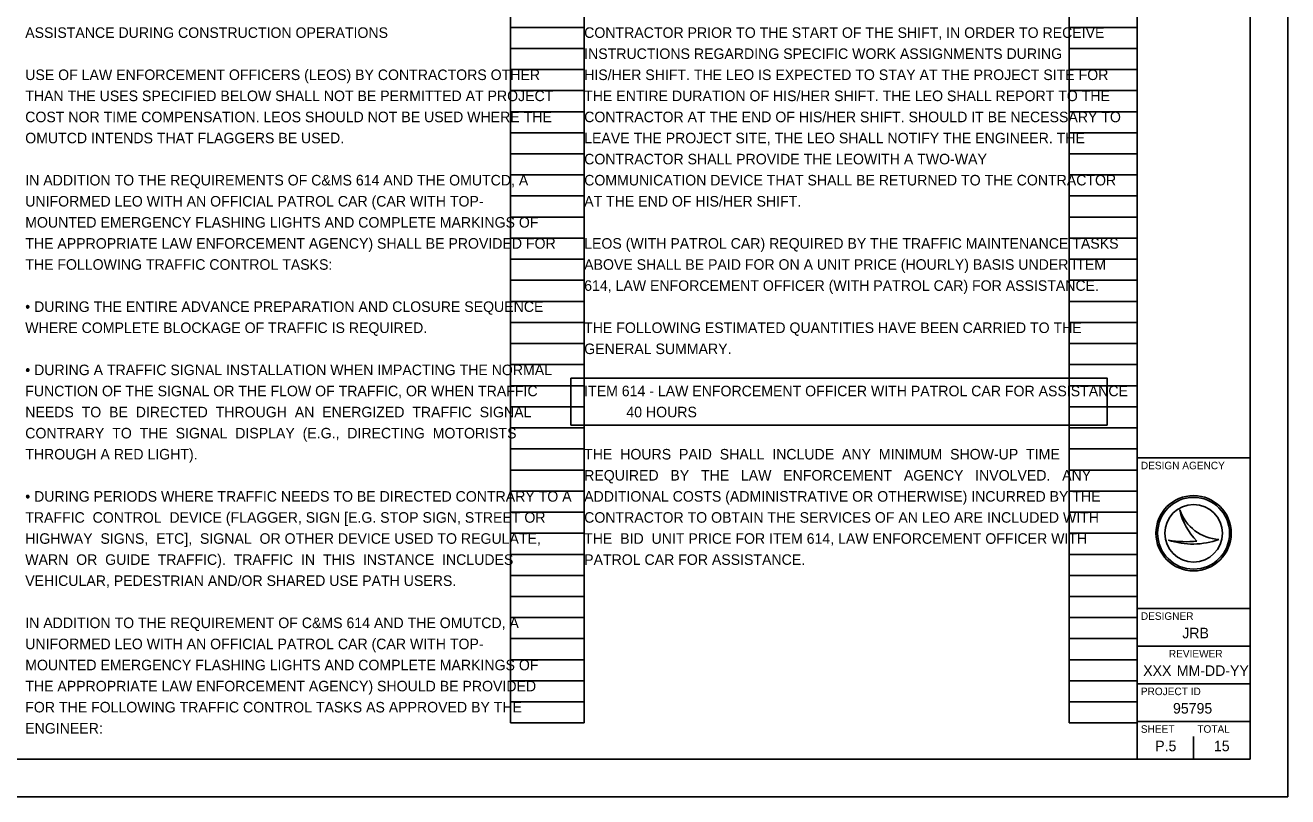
# Model space of a CAD drawing. Extents: x 0 to 34, y 0 to 22.
# Drawn here: x 17.24 to 34, y 0 to 10.25 of the extents above; entities that cross this region are included whole.
import ezdxf

# ---------------------------------------------------------------- set-up
doc = ezdxf.new("R2010")
doc.units = 0
for name, color, linetype in [('SC_Scratch1', 7, 'Continuous'), ('SH_Border', 7, 'Continuous'), ('SH_Cut_Line', 7, 'Continuous'), ('SH_Data', 7, 'Continuous'), ('SH_Text', 7, 'Continuous')]:
    doc.layers.add(name, color=color, linetype=linetype)

msp = doc.modelspace()

# ---------------------------------------------------------------- linework, layer by layer
at = {"layer": 'SC_Scratch1'}
msp.add_lwpolyline([(24.484, 5.562), (31.602, 5.562), (31.602, 4.936), (24.484, 4.936)], close=True, dxfattribs=at)
at = {"layer": 'SH_Border'}
for p, q in [((32, 0.5), (32, 21.5)), ((32, 4.5), (33.5, 4.5)), ((32, 2.5), (33.5, 2.5)), ((32, 2), (33.5, 2)), ((32, 1.5), (33.5, 1.5)), ((32, 1), (33.5, 1))]:
    msp.add_line(p, q, dxfattribs=at)
msp.add_lwpolyline([(1.5, 21.5), (33.5, 21.5), (33.5, 0.5), (1.5, 0.5)], close=True, dxfattribs=at)
at = {"layer": 'SH_Cut_Line'}
msp.add_lwpolyline([(0, 0), (34, 0), (34, 22), (0, 22)], close=True, dxfattribs=at)
at = {"layer": 'SH_Data'}
for p, q in [((23.68, 0.98), (23.68, 21.14)), ((24.66, 0.98), (24.66, 21.14)), ((31.1, 0.98), (31.1, 21.14)), ((32, 0.98), (32, 21.14)), ((23.68, 10.22), (24.66, 10.22)), ((31.1, 10.22), (32, 10.22)), ((23.68, 9.94), (24.66, 9.94)), ((31.1, 9.94), (32, 9.94)), ((23.68, 9.66), (24.66, 9.66)), ((31.1, 9.66), (32, 9.66)), ((23.68, 9.38), (24.66, 9.38)), ((31.1, 9.38), (32, 9.38)), ((23.68, 9.1), (24.66, 9.1)), ((31.1, 9.1), (32, 9.1)), ((23.68, 8.82), (24.66, 8.82)), ((31.1, 8.82), (32, 8.82)), ((23.68, 8.54), (24.66, 8.54)), ((31.1, 8.54), (32, 8.54)), ((23.68, 8.26), (24.66, 8.26)), ((31.1, 8.26), (32, 8.26)), ((23.68, 7.98), (24.66, 7.98)), ((31.1, 7.98), (32, 7.98)), ((23.68, 7.7), (24.66, 7.7)), ((31.1, 7.7), (32, 7.7)), ((23.68, 7.42), (24.66, 7.42)), ((31.1, 7.42), (32, 7.42)), ((23.68, 7.14), (24.66, 7.14)), ((31.1, 7.14), (32, 7.14)), ((23.68, 6.86), (24.66, 6.86)), ((31.1, 6.86), (32, 6.86)), ((23.68, 6.58), (24.66, 6.58)), ((31.1, 6.58), (32, 6.58)), ((23.68, 6.3), (24.66, 6.3)), ((31.1, 6.3), (32, 6.3)), ((23.68, 6.02), (24.66, 6.02)), ((31.1, 6.02), (32, 6.02)), ((23.68, 5.74), (24.66, 5.74)), ((31.1, 5.74), (32, 5.74)), ((23.68, 5.46), (24.66, 5.46)), ((31.1, 5.46), (32, 5.46)), ((23.68, 5.18), (24.66, 5.18)), ((31.1, 5.18), (32, 5.18)), ((23.68, 4.9), (24.66, 4.9)), ((31.1, 4.9), (32, 4.9)), ((23.68, 4.62), (24.66, 4.62)), ((31.1, 4.62), (32, 4.62)), ((23.68, 4.34), (24.66, 4.34)), ((31.1, 4.34), (32, 4.34)), ((23.68, 4.06), (24.66, 4.06)), ((31.1, 4.06), (32, 4.06)), ((23.68, 3.78), (24.66, 3.78)), ((31.1, 3.78), (32, 3.78)), ((32.567, 3.81), (32.567, 3.81)), ((23.68, 3.5), (24.66, 3.5)), ((31.1, 3.5), (32, 3.5)), ((32.417, 3.41), (32.417, 3.41)), ((32.75, 3.5), (32.75, 3.5)), ((33.087, 3.419), (33.087, 3.419)), ((23.68, 3.22), (24.66, 3.22)), ((31.1, 3.22), (32, 3.22)), ((23.68, 2.94), (24.66, 2.94)), ((31.1, 2.94), (32, 2.94)), ((23.68, 2.66), (24.66, 2.66)), ((31.1, 2.66), (32, 2.66)), ((23.68, 2.38), (24.66, 2.38)), ((31.1, 2.38), (32, 2.38)), ((23.68, 2.1), (24.66, 2.1)), ((31.1, 2.1), (32, 2.1)), ((23.68, 1.82), (24.66, 1.82)), ((31.1, 1.82), (32, 1.82)), ((23.68, 1.54), (24.66, 1.54)), ((31.1, 1.54), (32, 1.54)), ((23.68, 1.26), (24.66, 1.26)), ((31.1, 1.26), (32, 1.26)), ((23.68, 0.98), (24.66, 0.98)), ((31.1, 0.98), (32, 0.98)), ((32.375, 0.675), (32.375, 0.675)), ((32.75, 0.5), (32.75, 0.8))]:
    msp.add_line(p, q, dxfattribs=at)
for radius in [0.5, 0.477, 0.477, 0.382]:
    msp.add_circle((32.75, 3.5), radius, dxfattribs=at)
for centre, radius, start, end in [((33.116, 3.998), 0.58, 198.9257, 198.9319), ((33.347, 3.97), 0.796, 191.6379, 191.6421), ((33.116, 3.998), 0.58, 198.9319, 267.1657), ((33.347, 3.97), 0.796, 191.6421, 226.0947), ((32.739, 4.37), 1.013, 251.4576, 290.0832), ((32.648, 4.654), 1.266, 259.4964, 259.4995), ((32.739, 4.37), 1.013, 251.4527, 251.4576), ((32.648, 4.654), 1.266, 259.4995, 276.6672)]:
    msp.add_arc(centre, radius, start, end, dxfattribs=at)

# ---------------------------------------------------------------- texts
for s, height, p in [('DESIGN AGENCY', 0.1, (32.05, 4.35)), ('DESIGNER', 0.1, (32.05, 2.35)), ('JRB', 0.14, (32.6, 2.105)), ('REVIEWER', 0.1, (32.422, 1.85)), ('XXX', 0.14, (32.081, 1.605)), ('MM-DD-YY', 0.14, (32.527, 1.605)), ('PROJECT ID', 0.1, (32.05, 1.35)), ('95795', 0.14, (32.477, 1.105)), ('SHEET', 0.1, (32.05, 0.85)), ('TOTAL', 0.1, (32.8, 0.85)), ('P.5', 0.14, (32.241, 0.605)), ('15', 0.14, (33.02, 0.605))]:
    msp.add_text(s, height=height, dxfattribs=at).set_placement(p)
at = {"layer": 'SH_Text'}
for s, p in [('ASSISTANCE DURING CONSTRUCTION OPERATIONS', (17.24, 10.08)), ('CONTRACTOR PRIOR TO THE START OF THE SHIFT, IN ORDER TO RECEIVE', (24.66, 10.08)), ('INSTRUCTIONS REGARDING SPECIFIC WORK ASSIGNMENTS DURING', (24.66, 9.8)), ('USE OF LAW ENFORCEMENT OFFICERS (LEOS) BY CONTRACTORS OTHER', (17.24, 9.52)), ('HIS/HER SHIFT. THE LEO IS EXPECTED TO STAY AT THE PROJECT SITE FOR', (24.66, 9.52)), ('THE ENTIRE DURATION OF HIS/HER SHIFT. THE LEO SHALL REPORT TO THE', (24.66, 9.24)), ('THAN THE USES SPECIFIED BELOW SHALL NOT BE PERMITTED AT PROJECT', (17.24, 9.24)), ('COST NOR TIME COMPENSATION. LEOS SHOULD NOT BE USED WHERE THE', (17.24, 8.96)), ('CONTRACTOR AT THE END OF HIS/HER SHIFT. SHOULD IT BE NECESSARY TO', (24.66, 8.96)), ('OMUTCD INTENDS THAT FLAGGERS BE USED.', (17.24, 8.68)), ('LEAVE THE PROJECT SITE, THE LEO SHALL NOTIFY THE ENGINEER. THE', (24.66, 8.68)), ('CONTRACTOR SHALL PROVIDE THE LEOWITH A TWO-WAY', (24.66, 8.4)), ('IN ADDITION TO THE REQUIREMENTS OF C&MS 614 AND THE OMUTCD, A', (17.24, 8.12)), ('COMMUNICATION DEVICE THAT SHALL BE RETURNED TO THE CONTRACTOR', (24.66, 8.12)), ('UNIFORMED LEO WITH AN OFFICIAL PATROL CAR (CAR WITH TOP-', (17.24, 7.84)), ('AT THE END OF HIS/HER SHIFT.', (24.66, 7.84)), ('MOUNTED EMERGENCY FLASHING LIGHTS AND COMPLETE MARKINGS OF', (17.24, 7.56)), ('THE APPROPRIATE LAW ENFORCEMENT AGENCY) SHALL BE PROVIDED FOR', (17.24, 7.28)), ('LEOS (WITH PATROL CAR) REQUIRED BY THE TRAFFIC MAINTENANCE TASKS', (24.66, 7.28)), ('THE FOLLOWING TRAFFIC CONTROL TASKS:', (17.24, 7)), ('ABOVE SHALL BE PAID FOR ON A UNIT PRICE (HOURLY) BASIS UNDER ITEM', (24.66, 7)), ('614, LAW ENFORCEMENT OFFICER (WITH PATROL CAR) FOR ASSISTANCE.', (24.66, 6.72)), ('• DURING THE ENTIRE ADVANCE PREPARATION AND CLOSURE SEQUENCE', (17.24, 6.44)), ('WHERE COMPLETE BLOCKAGE OF TRAFFIC IS REQUIRED.', (17.24, 6.16)), ('THE FOLLOWING ESTIMATED QUANTITIES HAVE BEEN CARRIED TO THE', (24.66, 6.16)), ('GENERAL SUMMARY.', (24.66, 5.88)), ('• DURING A TRAFFIC SIGNAL INSTALLATION WHEN IMPACTING THE NORMAL', (17.24, 5.6)), ('FUNCTION OF THE SIGNAL OR THE FLOW OF TRAFFIC, OR WHEN TRAFFIC', (17.24, 5.32)), ('ITEM 614 - LAW ENFORCEMENT OFFICER WITH PATROL CAR FOR ASSISTANCE', (24.66, 5.32)), ('NEEDS  TO  BE  DIRECTED  THROUGH  AN  ENERGIZED  TRAFFIC  SIGNAL', (17.24, 5.04)), ('40 HOURS', (25.22, 5.04)), ('CONTRARY  TO  THE  SIGNAL  DISPLAY  (E.G.,  DIRECTING  MOTORISTS', (17.24, 4.76)), ('THROUGH A RED LIGHT).', (17.24, 4.48)), ('THE  HOURS  PAID  SHALL  INCLUDE  ANY  MINIMUM  SHOW-UP  TIME', (24.66, 4.48)), ('REQUIRED   BY   THE   LAW   ENFORCEMENT   AGENCY   INVOLVED.   ANY', (24.66, 4.2)), ('• DURING PERIODS WHERE TRAFFIC NEEDS TO BE DIRECTED CONTRARY TO A', (17.24, 3.92)), ('ADDITIONAL COSTS (ADMINISTRATIVE OR OTHERWISE) INCURRED BY THE', (24.66, 3.92)), ('TRAFFIC  CONTROL  DEVICE (FLAGGER, SIGN [E.G. STOP SIGN, STREET OR', (17.24, 3.64)), ('CONTRACTOR TO OBTAIN THE SERVICES OF AN LEO ARE INCLUDED WITH', (24.66, 3.64)), ('HIGHWAY  SIGNS,  ETC],  SIGNAL  OR OTHER DEVICE USED TO REGULATE,', (17.24, 3.36)), ('THE  BID  UNIT PRICE FOR ITEM 614, LAW ENFORCEMENT OFFICER WITH', (24.66, 3.36)), ('WARN  OR  GUIDE  TRAFFIC).  TRAFFIC  IN  THIS  INSTANCE  INCLUDES', (17.24, 3.08)), ('PATROL CAR FOR ASSISTANCE.', (24.66, 3.08)), ('VEHICULAR, PEDESTRIAN AND/OR SHARED USE PATH USERS.', (17.24, 2.8)), ('IN ADDITION TO THE REQUIREMENT OF C&MS 614 AND THE OMUTCD, A', (17.24, 2.24)), ('UNIFORMED LEO WITH AN OFFICIAL PATROL CAR (CAR WITH TOP-', (17.24, 1.96)), ('MOUNTED EMERGENCY FLASHING LIGHTS AND COMPLETE MARKINGS OF', (17.24, 1.68)), ('THE APPROPRIATE LAW ENFORCEMENT AGENCY) SHOULD BE PROVIDED', (17.24, 1.4)), ('FOR THE FOLLOWING TRAFFIC CONTROL TASKS AS APPROVED BY THE', (17.24, 1.12)), ('ENGINEER:', (17.24, 0.84))]:
    msp.add_text(s, height=0.14, dxfattribs=at).set_placement(p)

doc.saveas('drawing.dxf')
